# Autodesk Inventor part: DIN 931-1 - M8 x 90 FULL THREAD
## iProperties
IsCustomPart: 1
Created: 2006-02
Part Number: DIN 931-1 - M8 x 90 FULL THREAD
Material: Steel, Mild
Description: Hex-Head Bolt
Document SubType Name: Modeling
Standard: DIN 931-1
Designer: Andy Moles
Standards Organization: DIN
Language: en-US
Size Designation: M8 x 80
Categories: <MemberInstance><Categories><Category DisplayName="Fasteners" InternalName="e4da775c-781d-43d5-af7c-5136215cf5a6" Mnemonic="FSTN"><Category DisplayName="Bolts"
Density: 1 g/cm^3
Author: Andy Moles
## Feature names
1. Body [Revolution]
2. Head [Extrusion]
3. Chamfer1 [Revolution]
4. Chamfer2
